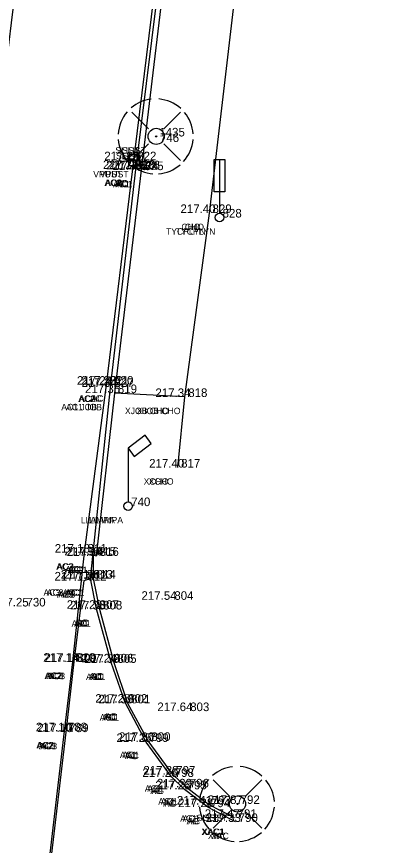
# Model space of a CAD drawing. Extents: x -471047 to -470889, y -1102859 to -1102000.
# Drawn here: x -470978.51 to -470961.14, y -1102637.38 to -1102598.73 of the extents above; entities that cross this region are included whole.
import ezdxf

# ---------------------------------------------------------------- set-up
doc = ezdxf.new("R2010")
doc.units = 0
for name, color, linetype in [('Vrstva 1', 7, 'Continuous'), ('Vrstva 11', 7, 'Continuous'), ('Vrstva 16', 7, 'Continuous'), ('Vrstva 23', 7, 'Continuous'), ('Vrstva 25', 7, 'Continuous'), ('Vrstva 34', 7, 'Continuous'), ('Vrstva 35', 7, 'Continuous'), ('Vrstva 36', 7, 'Continuous'), ('Vrstva 38', 7, 'Continuous'), ('Vrstva 5', 7, 'Continuous'), ('Vrstva 7', 7, 'Continuous'), ('Vrstva 8', 7, 'Continuous')]:
    doc.layers.add(name, color=color, linetype=linetype)

msp = doc.modelspace()

# ---------------------------------------------------------------- linework, layer by layer
at = {"layer": 'Vrstva 1'}
for points in [[(-471040.344, -1102858.385), (-471031.676, -1102846.187), (-471026.357, -1102838.629), (-471023.212, -1102833.975), (-471019.21, -1102827.465), (-471016.861, -1102823.272), (-471013.099, -1102815.912), (-471010.824, -1102810.955), (-471007.329, -1102802.292), (-471005.34, -1102796.515), (-471002.842, -1102787.838), (-471001.3, -1102780.997), (-471000.19, -1102774.713), (-470999.247, -1102768.204), (-470998.794, -1102764.784), (-470997.199, -1102751.812), (-470994.899, -1102732.807), (-470992.551, -1102713.262), (-470990.326, -1102694.887), (-470988.122, -1102676.57), (-470985.812, -1102657.305), (-470983.537, -1102638.407), (-470981.386, -1102620.622), (-470979.843, -1102608.014), (-470976.377, -1102579.253), (-470972.945, -1102550.69), (-470970.475, -1102530.206), (-470967.905, -1102508.801), (-470965.053, -1102485.131), (-470962.734, -1102465.9), (-470960.173, -1102444.812), (-470957.795, -1102425.103), (-470954.965, -1102401.839), (-470953.834, -1102392.574), (-470952.33, -1102379.985), (-470950.744, -1102366.853), (-470948.978, -1102352.106), (-470947.037, -1102335.844), (-470944.949, -1102318.462), (-470944.013, -1102310.745), (-470942.39, -1102297.267), (-470939.519, -1102273.45), (-470937.593, -1102257.43), (-470936.064, -1102244.81), (-470934.114, -1102228.634), (-470931.621, -1102207.856), (-470929.536, -1102190.857), (-470926.572, -1102166.31), (-470924.91, -1102152.663), (-470923.413, -1102140.333), (-470921.923, -1102127.669), (-470921.155, -1102120.084), (-470920.446, -1102109.574), (-470919.912, -1102099.137), (-470919.63, -1102088.981), (-470919.523, -1102081.193), (-470919.563, -1102070.395), (-470919.714, -1102064.236), (-470920.134, -1102054.704), (-470920.462, -1102047.615), (-470920.599, -1102044.52), (-470920.743, -1102041.873), (-470921.125, -1102034.455), (-470921.774, -1102030.337), (-470922.418, -1102027.787), (-470923.734, -1102023.93), (-470924.872, -1102021.434), (-470926.752, -1102018.182), (-470927.953, -1102016.45), (-470929.616, -1102014.424), (-470932.252, -1102011.756), (-470935.111, -1102009.425), (-470938.391, -1102007.371), (-470942.651, -1102005.401)], [(-471041.328, -1102857.18), (-471032.144, -1102844.242), (-471027.583, -1102837.763), (-471024.388, -1102833.028), (-471020.451, -1102826.6), (-471018.089, -1102822.378), (-471014.542, -1102815.445), (-471012.233, -1102810.418), (-471009.247, -1102803.108), (-471006.795, -1102796.098), (-471004.315, -1102787.532), (-471002.782, -1102780.723), (-471001.674, -1102774.458), (-471000.75, -1102768.095), (-471000.28, -1102764.601), (-470998.692, -1102751.741), (-470996.378, -1102732.635), (-470994.028, -1102713.058), (-470991.808, -1102694.749), (-470989.616, -1102676.447), (-470987.284, -1102657.013), (-470985.031, -1102638.272), (-470982.87, -1102620.431), (-470981.334, -1102607.933), (-470977.881, -1102579.263), (-470974.429, -1102550.492), (-470971.964, -1102530.054), (-470969.391, -1102508.607), (-470966.54, -1102484.984), (-470964.231, -1102465.853), (-470961.679, -1102444.752), (-470959.304, -1102425.078), (-470956.455, -1102401.634), (-470955.339, -1102392.489), (-470953.812, -1102379.71), (-470952.249, -1102366.808), (-470950.479, -1102352.023), (-470948.536, -1102335.868), (-470946.426, -1102318.233), (-470945.493, -1102310.531), (-470943.864, -1102297.013), (-470940.984, -1102273.071), (-470939.078, -1102257.195), (-470937.559, -1102244.684), (-470935.592, -1102228.353), (-470933.101, -1102207.653), (-470931.011, -1102190.57), (-470928.046, -1102166.021), (-470926.409, -1102152.578), (-470924.898, -1102140.121), (-470923.427, -1102127.544), (-470922.647, -1102119.826), (-470921.919, -1102109.229), (-470921.42, -1102099.134), (-470921.127, -1102089.016), (-470921.023, -1102081.453), (-470921.061, -1102070.468), (-470921.209, -1102064.314), (-470921.666, -1102053.966), (-470922.156, -1102043.345), (-470922.299, -1102039.934), (-470922.637, -1102034.36), (-470923.091, -1102031.241), (-470923.847, -1102028.247), (-470925.083, -1102024.594), (-470926.222, -1102022.086), (-470928.04, -1102018.943), (-470929.138, -1102017.357), (-470930.929, -1102015.175), (-470933.062, -1102013.049), (-470936.379, -1102010.368), (-470939.169, -1102008.662), (-470942.899, -1102006.906), (-470945.661, -1102005.908)], [(-471043.557, -1102855.955), (-471035.129, -1102844.026), (-471029.872, -1102836.499), (-471026.577, -1102831.578), (-471022.675, -1102825.415), (-471020.123, -1102821.053), (-471016.667, -1102814.59), (-471014.208, -1102809.45), (-471011.177, -1102802.451), (-471008.55, -1102795.333), (-471006.082, -1102787.209), (-471004.464, -1102780.376), (-471003.265, -1102774.167), (-471002.327, -1102767.948), (-471001.636, -1102762.527), (-471000.297, -1102751.605), (-470997.959, -1102732.524), (-470995.602, -1102712.802), (-470993.412, -1102694.623), (-470991.21, -1102676.17), (-470988.891, -1102656.857), (-470986.625, -1102638.083), (-470984.455, -1102620.195), (-470982.936, -1102607.733), (-470979.497, -1102579.223), (-470976.023, -1102550.279), (-470973.554, -1102529.822), (-470970.991, -1102508.497), (-470968.146, -1102484.787), (-470965.835, -1102465.72), (-470963.284, -1102444.529), (-470960.91, -1102424.942), (-470958.043, -1102401.343), (-470956.946, -1102392.356), (-470955.396, -1102379.408), (-470953.851, -1102366.636), (-470952.049, -1102351.733), (-470950.124, -1102335.611), (-470948.034, -1102318.083), (-470947.094, -1102310.328), (-470945.421, -1102296.51), (-470942.58, -1102272.848), (-470940.675, -1102256.948), (-470939.176, -1102244.526), (-470937.187, -1102228.174), (-470934.708, -1102207.467), (-470932.621, -1102190.433), (-470929.634, -1102165.778), (-470928.004, -1102152.415), (-470926.45, -1102139.595), (-470925.003, -1102127.418), (-470924.249, -1102119.695), (-470923.515, -1102109.093), (-470923.018, -1102099.069), (-470922.711, -1102088.911), (-470922.643, -1102081.356), (-470922.797, -1102070.414), (-470923.018, -1102064.454), (-470923.52, -1102053.203), (-470923.823, -1102047.529), (-470924.123, -1102041.506), (-470924.462, -1102037.486), (-470924.934, -1102031.904), (-470925.664, -1102028.672), (-470926.771, -1102025.506), (-470927.959, -1102022.914), (-470929.674, -1102020.028), (-470930.76, -1102018.498), (-470932.447, -1102016.478), (-470935.215, -1102013.816), (-470937.644, -1102011.98), (-470940.381, -1102010.371), (-470943.968, -1102008.669), (-470947.145, -1102007.524), (-470950.874, -1102006.74)], [(-471044.756, -1102855.056), (-471036.376, -1102843.177), (-471031.167, -1102835.741), (-471027.859, -1102830.8), (-471023.934, -1102824.593), (-471021.43, -1102820.312), (-471018.011, -1102813.91), (-471015.536, -1102808.75), (-471012.578, -1102801.897), (-471009.95, -1102794.77), (-471007.561, -1102786.914), (-471005.936, -1102780.074), (-471004.727, -1102773.818), (-471003.828, -1102767.827), (-471003.121, -1102762.345), (-471001.787, -1102751.467), (-470999.446, -1102732.348), (-470997.073, -1102712.539), (-470994.902, -1102694.521), (-470992.696, -1102676.023), (-470990.376, -1102656.68), (-470988.131, -1102638.071), (-470985.947, -1102620.018), (-470984.417, -1102607.512), (-470980.993, -1102579.08), (-470977.514, -1102550.137), (-470975.048, -1102529.649), (-470972.488, -1102508.37), (-470969.618, -1102484.508), (-470967.34, -1102465.669), (-470964.767, -1102444.39), (-470962.402, -1102424.781), (-470959.534, -1102401.193), (-470958.432, -1102392.151), (-470956.883, -1102379.208), (-470955.335, -1102366.424), (-470953.535, -1102351.506), (-470951.606, -1102335.399), (-470949.519, -1102317.94), (-470948.575, -1102310.159), (-470946.889, -1102296.144), (-470944.056, -1102272.618), (-470942.139, -1102256.659), (-470940.657, -1102244.341), (-470938.638, -1102227.749), (-470936.19, -1102207.298), (-470934.102, -1102190.255), (-470931.124, -1102165.639), (-470929.492, -1102152.254), (-470927.915, -1102139.252), (-470926.46, -1102127.103), (-470925.74, -1102119.604), (-470925.012, -1102108.913), (-470924.523, -1102099.054), (-470924.217, -1102088.866), (-470924.148, -1102081.334), (-470924.301, -1102070.391), (-470924.518, -1102064.43), (-470924.97, -1102054.435), (-470925.588, -1102041.569), (-470925.963, -1102035.313), (-470926.405, -1102032.225), (-470927.078, -1102029.198), (-470928.123, -1102026.148), (-470929.318, -1102023.558), (-470930.84, -1102020.97), (-470931.868, -1102019.515), (-470933.443, -1102017.605), (-470936.26, -1102014.885), (-470938.429, -1102013.255), (-470941.213, -1102011.639), (-470944.847, -1102009.927), (-470947.723, -1102008.912), (-470951.444, -1102008.161), (-470954.511, -1102007.931), (-470957.895, -1102008.041)]]:
    msp.add_spline(points, degree=3, dxfattribs=at)
at = {"layer": 'Vrstva 11'}
msp.add_line((-470969.056, -1102605.402), (-470969.056, -1102607.902), dxfattribs=at)
msp.add_lwpolyline([(-470969.306, -1102605.402), (-470968.806, -1102605.402), (-470968.806, -1102606.902), (-470969.306, -1102606.902)], close=True, dxfattribs=at)
msp.add_circle((-470969.056, -1102608.101), 0.2, dxfattribs=at)
at = {"layer": 'Vrstva 16'}
for p, q in [((-470972.362, -1102603.961), (-470973.136, -1102603.186)), ((-470971.652, -1102603.961), (-470970.876, -1102603.186)), ((-470972.362, -1102604.671), (-470973.136, -1102605.446)), ((-470971.652, -1102604.671), (-470970.876, -1102605.446)), ((-470968.574, -1102635.096), (-470969.348, -1102634.321)), ((-470967.864, -1102635.096), (-470967.088, -1102634.321)), ((-470968.574, -1102635.806), (-470969.348, -1102636.581)), ((-470967.864, -1102635.806), (-470967.088, -1102636.581))]:
    msp.add_line(p, q, dxfattribs=at)
for centre, radius in [((-470972.006, -1102604.316), 0.375), ((-470972.006, -1102604.316), 0.025), ((-470972.006, -1102604.316), 0.025), ((-470968.218, -1102635.451), 0.375), ((-470968.218, -1102635.451), 0.025), ((-470968.218, -1102635.451), 0.025)]:
    msp.add_circle(centre, radius, dxfattribs=at)
for centre, start, end in [((-470972.031, -1102604.316), 96.7144, 130.447), ((-470972.031, -1102604.316), 48.1897, 84.9117), ((-470972.031, -1102604.316), 139.23, 176.4602), ((-470972.031, -1102604.316), 3.8615, 39.6013), ((-470972.031, -1102604.316), 184.9408, 222.2827), ((-470972.031, -1102604.316), 318.1086, 355.0481), ((-470972.031, -1102604.316), 274.1732, 310.7861), ((-470972.031, -1102604.316), 230.4703, 265.8356), ((-470968.243, -1102635.451), 96.7144, 130.447), ((-470968.243, -1102635.451), 48.1897, 84.9117), ((-470968.243, -1102635.451), 139.23, 176.4602), ((-470968.243, -1102635.451), 3.8615, 39.6013), ((-470968.243, -1102635.451), 184.9408, 222.2827), ((-470968.243, -1102635.451), 318.1086, 355.0481), ((-470968.243, -1102635.451), 230.4703, 265.8356), ((-470968.243, -1102635.451), 274.1732, 310.7861)]:
    msp.add_arc(centre, 1.75, start, end, dxfattribs=at)
at = {"layer": 'Vrstva 23'}
for p, q in [((-470972.523, -1102618.257), (-470973.318, -1102618.862)), ((-470972.233, -1102618.634), (-470972.523, -1102618.257)), ((-470973.03, -1102619.24), (-470972.233, -1102618.634)), ((-470973.318, -1102618.862), (-470973.318, -1102621.362)), ((-470973.318, -1102618.862), (-470973.03, -1102619.24))]:
    msp.add_line(p, q, dxfattribs=at)
msp.add_circle((-470973.318, -1102621.562), 0.2, dxfattribs=at)
at = {"layer": 'Vrstva 25'}
for p, q in [((-470973.29, -1102605.181), (-470973.29, -1102605.681)), ((-470972.79, -1102605.181), (-470973.29, -1102605.181)), ((-470972.79, -1102605.681), (-470972.79, -1102605.181)), ((-470973.29, -1102605.431), (-470972.79, -1102605.431)), ((-470973.29, -1102605.681), (-470972.79, -1102605.681))]:
    msp.add_line(p, q, dxfattribs=at)
at = {"layer": 'Vrstva 34'}
for p, q in [((-470972.01, -1102604.32), (-470972.01, -1102604.32)), ((-470971.98, -1102604.58), (-470971.98, -1102604.58)), ((-470973.04, -1102605.43), (-470973.04, -1102605.43)), ((-470973.1, -1102605.83), (-470973.1, -1102605.83)), ((-470972.95, -1102605.86), (-470972.95, -1102605.86)), ((-470972.87, -1102605.85), (-470972.87, -1102605.85)), ((-470972.7, -1102605.89), (-470972.7, -1102605.89)), ((-470969.53, -1102607.89), (-470969.53, -1102607.89)), ((-470969.06, -1102608.1), (-470969.06, -1102608.1)), ((-470974.32, -1102615.9), (-470974.32, -1102615.9)), ((-470974.11, -1102615.89), (-470974.11, -1102615.89)), ((-470974.1, -1102616), (-470974.1, -1102616)), ((-470973.94, -1102616.29), (-470973.94, -1102616.29)), ((-470970.66, -1102616.47), (-470970.66, -1102616.47)), ((-470970.99, -1102619.76), (-470970.99, -1102619.76)), ((-470973.32, -1102621.56), (-470973.32, -1102621.56)), ((-470975.35, -1102623.73), (-470975.35, -1102623.73)), ((-470974.92, -1102623.86), (-470974.92, -1102623.86)), ((-470974.79, -1102623.88), (-470974.79, -1102623.88)), ((-470975.07, -1102624.94), (-470975.07, -1102624.94)), ((-470974.93, -1102624.94), (-470974.93, -1102624.94)), ((-470975.36, -1102625.03), (-470975.36, -1102625.03)), ((-470971.31, -1102625.93), (-470971.31, -1102625.93)), ((-470978.2, -1102626.24), (-470978.2, -1102626.24)), ((-470974.79, -1102626.35), (-470974.79, -1102626.35)), ((-470974.63, -1102626.38), (-470974.63, -1102626.38)), ((-470975.89, -1102628.82), (-470975.89, -1102628.82)), ((-470975.83, -1102628.83), (-470975.83, -1102628.83)), ((-470974.11, -1102628.85), (-470974.11, -1102628.85)), ((-470973.96, -1102628.87), (-470973.96, -1102628.87)), ((-470973.46, -1102630.73), (-470973.46, -1102630.73)), ((-470973.32, -1102630.76), (-470973.32, -1102630.76)), ((-470970.57, -1102631.12), (-470970.57, -1102631.12)), ((-470976.27, -1102632.06), (-470976.27, -1102632.06)), ((-470976.2, -1102632.1), (-470976.2, -1102632.1)), ((-470972.47, -1102632.56), (-470972.47, -1102632.56)), ((-470972.38, -1102632.51), (-470972.38, -1102632.51)), ((-470971.29, -1102634.19), (-470971.29, -1102634.19)), ((-470971.22, -1102634.08), (-470971.22, -1102634.08)), ((-470970.69, -1102634.77), (-470970.69, -1102634.77)), ((-470970.59, -1102634.68), (-470970.59, -1102634.68)), ((-470969.6, -1102635.6), (-470969.6, -1102635.6)), ((-470969.57, -1102635.48), (-470969.57, -1102635.48)), ((-470968.22, -1102635.45), (-470968.22, -1102635.45)), ((-470968.36, -1102636.1), (-470968.36, -1102636.1)), ((-470968.31, -1102636.29), (-470968.31, -1102636.29))]:
    msp.add_line(p, q, dxfattribs=at)
at = {"layer": 'Vrstva 5'}
for p, q in [((-470973.102, -1102605.831), (-470971.829, -1102595.558)), ((-470974.316, -1102615.896), (-470973.102, -1102605.831)), ((-470975.354, -1102623.727), (-470974.316, -1102615.896)), ((-470975.893, -1102628.817), (-470975.354, -1102623.727)), ((-470976.273, -1102632.056), (-470975.893, -1102628.817)), ((-470977.18, -1102639.695), (-470976.273, -1102632.056))]:
    msp.add_line(p, q, dxfattribs=at)
at = {"layer": 'Vrstva 7'}
for p, q in [((-470972.697, -1102605.89), (-470971.45, -1102595.6)), ((-470973.941, -1102616.294), (-470972.697, -1102605.89)), ((-470974.792, -1102623.875), (-470973.941, -1102616.294)), ((-470974.926, -1102624.937), (-470974.925, -1102623.855)), ((-470974.925, -1102623.855), (-470974.792, -1102623.875)), ((-470974.632, -1102626.381), (-470974.926, -1102624.937)), ((-470973.964, -1102628.866), (-470974.632, -1102626.381)), ((-470973.322, -1102630.758), (-470973.964, -1102628.866)), ((-470972.382, -1102632.514), (-470973.322, -1102630.758)), ((-470971.223, -1102634.075), (-470972.382, -1102632.514)), ((-470970.595, -1102634.678), (-470971.223, -1102634.075)), ((-470969.568, -1102635.483), (-470970.595, -1102634.678)), ((-470968.356, -1102636.102), (-470969.568, -1102635.483))]:
    msp.add_line(p, q, dxfattribs=at)
at = {"layer": 'Vrstva 8'}
for p, q in [((-470972.95, -1102605.858), (-470971.694, -1102595.593)), ((-470969.526, -1102607.892), (-470968.026, -1102595.232)), ((-470974.114, -1102615.891), (-470972.95, -1102605.858)), ((-470970.664, -1102616.465), (-470969.526, -1102607.892)), ((-470975.066, -1102624.94), (-470974.114, -1102615.891)), ((-470970.664, -1102616.465), (-470973.941, -1102616.294)), ((-470970.991, -1102619.76), (-470970.664, -1102616.465)), ((-470975.362, -1102625.028), (-470975.066, -1102624.94)), ((-470974.789, -1102626.351), (-470975.066, -1102624.94)), ((-470975.83, -1102628.827), (-470975.362, -1102625.028)), ((-470974.11, -1102628.847), (-470974.789, -1102626.351)), ((-470976.199, -1102632.1), (-470975.83, -1102628.827)), ((-470973.459, -1102630.725), (-470974.11, -1102628.847)), ((-470972.473, -1102632.563), (-470973.459, -1102630.725)), ((-470977.108, -1102639.699), (-470976.199, -1102632.1)), ((-470971.287, -1102634.191), (-470972.473, -1102632.563)), ((-470970.691, -1102634.769), (-470971.287, -1102634.191)), ((-470969.601, -1102635.601), (-470970.691, -1102634.769)), ((-470968.308, -1102636.291), (-470969.601, -1102635.601))]:
    msp.add_line(p, q, dxfattribs=at)

# ---------------------------------------------------------------- texts
at = {"layer": 'Vrstva 35'}
for s, p in [('SLIST', (-470973.91, -1102605.12)), ('SLIST', (-470973.599, -1102605.12)), ('SLIST', (-470973.88, -1102605.38)), ('SLIST', (-470973.569, -1102605.38)), ('VPUST', (-470974.94, -1102606.23)), ('VPUST', (-470974.629, -1102606.23)), ('AC2', (-470974.416, -1102606.63)), ('AC2', (-470974.375, -1102606.63)), ('AC1', (-470974.017, -1102606.69)), ('AC', (-470973.939, -1102606.66)), ('AC1', (-470973.9, -1102606.69)), ('AC', (-470973.864, -1102606.66)), ('TYCPLYN', (-470971.549, -1102608.9)), ('TYCPLYN', (-470971.099, -1102608.9)), ('CHO', (-470970.831, -1102608.69)), ('CHO', (-470970.669, -1102608.69)), ('AC2', (-470975.636, -1102616.7)), ('AC2', (-470975.595, -1102616.7)), ('AC', (-470975.099, -1102616.69)), ('AC', (-470975.024, -1102616.69)), ('AC1 JOB', (-470976.429, -1102617.09)), ('AC1 JOB', (-470976.204, -1102617.09)), ('XJOB CHO', (-470973.461, -1102617.27)), ('XJOB CHO', (-470972.924, -1102617.27)), ('XCHO', (-470972.591, -1102620.56)), ('XCHO', (-470972.354, -1102620.56)), ('LLAMPA', (-470975.52, -1102622.36)), ('LLAMPA', (-470975.134, -1102622.36)), ('AC2', (-470976.666, -1102624.53)), ('AC2', (-470976.625, -1102624.53)), ('AC1', (-470976.237, -1102624.66)), ('AC1', (-470976.12, -1102624.66)), ('AC1', (-470976.107, -1102624.68)), ('AC1', (-470975.99, -1102624.68)), ('AC3 AC', (-470977.259, -1102625.74)), ('AC3 AC', (-470977.109, -1102625.74)), ('AC3', (-470976.635, -1102625.83)), ('AC3', (-470976.563, -1102625.83)), ('AC1', (-470976.247, -1102625.74)), ('AC1', (-470976.13, -1102625.74)), ('AC1', (-470975.947, -1102627.18)), ('AC1', (-470975.83, -1102627.18)), ('AC', (-470975.779, -1102627.15)), ('AC', (-470975.704, -1102627.15)), ('AC2', (-470977.206, -1102629.62)), ('AC2', (-470977.165, -1102629.62)), ('AC3', (-470977.105, -1102629.63)), ('AC3', (-470977.033, -1102629.63)), ('AC1', (-470975.277, -1102629.67)), ('AC1', (-470975.16, -1102629.67)), ('AC', (-470975.099, -1102629.65)), ('AC', (-470975.024, -1102629.65)), ('AC1', (-470974.637, -1102631.56)), ('AC1', (-470974.52, -1102631.56)), ('AC', (-470974.449, -1102631.53)), ('AC', (-470974.374, -1102631.53)), ('AC2', (-470977.586, -1102632.86)), ('AC2', (-470977.545, -1102632.86)), ('AC3', (-470977.475, -1102632.9)), ('AC3', (-470977.403, -1102632.9)), ('AC1', (-470973.697, -1102633.31)), ('AC1', (-470973.58, -1102633.31)), ('AC', (-470973.459, -1102633.36)), ('AC', (-470973.384, -1102633.36)), ('AC1', (-470972.537, -1102634.88)), ('AC1', (-470972.42, -1102634.88)), ('AC', (-470972.279, -1102634.99)), ('AC', (-470972.204, -1102634.99)), ('AC1', (-470971.907, -1102635.48)), ('AC1', (-470971.79, -1102635.48)), ('AC', (-470971.679, -1102635.57)), ('AC', (-470971.604, -1102635.57)), ('AC1', (-470970.887, -1102636.28)), ('AC1', (-470970.77, -1102636.28)), ('AC', (-470970.589, -1102636.4)), ('AC', (-470970.514, -1102636.4)), ('SLIST', (-470970.12, -1102636.25)), ('SLIST', (-470969.809, -1102636.25)), ('XAC1', (-470969.902, -1102636.9)), ('XAC1', (-470969.86, -1102636.9)), ('XAC', (-470969.599, -1102637.09)), ('XAC', (-470969.449, -1102637.09))]:
    msp.add_text(s, height=0.3, dxfattribs=at).set_placement(p)
at = {"layer": 'Vrstva 36'}
for s, p in [(' 1435', (-470972.01, -1102604.32)), (' 746', (-470971.98, -1102604.58)), (' 822', (-470973.04, -1102605.43)), (' 823', (-470973.1, -1102605.83)), (' 824', (-470972.95, -1102605.86)), (' 826', (-470972.87, -1102605.85)), (' 825', (-470972.7, -1102605.89)), (' 829', (-470969.53, -1102607.89)), (' 828', (-470969.06, -1102608.1)), (' 821', (-470974.32, -1102615.9)), (' 820', (-470974.11, -1102615.89)), (' 827', (-470974.1, -1102616)), (' 819', (-470973.94, -1102616.29)), (' 818', (-470970.66, -1102616.47)), (' 817', (-470970.99, -1102619.76)), (' 740', (-470973.32, -1102621.56)), (' 811', (-470975.35, -1102623.73)), (' 815', (-470974.92, -1102623.86)), (' 816', (-470974.79, -1102623.88)), (' 813', (-470975.07, -1102624.94)), (' 814', (-470974.93, -1102624.94)), (' 812', (-470975.36, -1102625.03)), (' 804', (-470971.31, -1102625.93)), (' 730', (-470978.2, -1102626.24)), (' 807', (-470974.79, -1102626.35)), (' 808', (-470974.63, -1102626.38)), (' 810', (-470975.89, -1102628.82)), (' 809', (-470975.83, -1102628.83)), (' 806', (-470974.11, -1102628.85)), (' 805', (-470973.96, -1102628.87)), (' 802', (-470973.46, -1102630.73)), (' 801', (-470973.32, -1102630.76)), (' 803', (-470970.57, -1102631.12)), (' 788', (-470976.27, -1102632.06)), (' 789', (-470976.2, -1102632.1)), (' 799', (-470972.47, -1102632.56)), (' 800', (-470972.38, -1102632.51)), (' 798', (-470971.29, -1102634.19)), (' 797', (-470971.22, -1102634.08)), (' 795', (-470970.69, -1102634.77)), (' 796', (-470970.59, -1102634.68)), (' 794', (-470969.6, -1102635.6)), (' 793', (-470969.57, -1102635.48)), (' 792', (-470968.22, -1102635.45)), (' 791', (-470968.36, -1102636.1)), (' 790', (-470968.31, -1102636.29))]:
    msp.add_text(s, height=0.4, dxfattribs=at).set_placement(p)
at = {"layer": 'Vrstva 38'}
for s, p in [('217.25 ', (-470974.424, -1102605.43)), ('217.28 ', (-470974.484, -1102605.83)), ('217.29 ', (-470974.334, -1102605.86)), ('217.40 ', (-470974.213, -1102605.85)), ('217.40 ', (-470974.043, -1102605.89)), ('217.40 ', (-470970.873, -1102607.89)), ('217.24 ', (-470975.702, -1102615.9)), ('217.23 ', (-470975.493, -1102615.89)), ('217.34 ', (-470975.482, -1102616)), ('217.35 ', (-470975.324, -1102616.29)), ('217.34 ', (-470972.042, -1102616.47)), ('217.40 ', (-470972.333, -1102619.76)), ('217.18 ', (-470976.734, -1102623.73)), ('217.36 ', (-470976.28, -1102623.86)), ('217.34 ', (-470976.172, -1102623.88)), ('217.18 ', (-470976.454, -1102624.94)), ('217.36 ', (-470976.29, -1102624.94)), ('217.17 ', (-470976.743, -1102625.03)), ('217.54 ', (-470972.692, -1102625.93)), ('217.25 ', (-470979.584, -1102626.24)), ('217.23 ', (-470976.173, -1102626.35)), ('217.38 ', (-470976.014, -1102626.38)), ('217.14 ', (-470977.272, -1102628.82)), ('217.14 ', (-470977.212, -1102628.83)), ('217.24 ', (-470975.492, -1102628.85)), ('217.39 ', (-470975.344, -1102628.87)), ('217.25 ', (-470974.844, -1102630.73)), ('217.39 ', (-470974.704, -1102630.76)), ('217.64 ', (-470971.952, -1102631.12)), ('217.10 ', (-470977.613, -1102632.06)), ('217.10 ', (-470977.543, -1102632.1)), ('217.25 ', (-470973.854, -1102632.56)), ('217.36 ', (-470973.74, -1102632.51)), ('217.26 ', (-470972.65, -1102634.19)), ('217.38 ', (-470972.604, -1102634.08)), ('217.26 ', (-470972.05, -1102634.77)), ('217.39 ', (-470971.974, -1102634.68)), ('217.41 ', (-470971.04, -1102635.48)), ('217.28 ', (-470970.984, -1102635.6)), ('217.87 ', (-470969.603, -1102635.45)), ('217.47 ', (-470969.743, -1102636.1)), ('217.33 ', (-470969.693, -1102636.29))]:
    msp.add_text(s, height=0.4, dxfattribs=at).set_placement(p)

doc.saveas('drawing.dxf')
